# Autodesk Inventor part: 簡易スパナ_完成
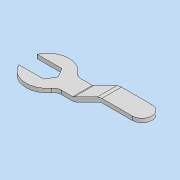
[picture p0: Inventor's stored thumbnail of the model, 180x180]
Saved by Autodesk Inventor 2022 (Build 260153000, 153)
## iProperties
Created: 2021-07
Part Number: 簡易スパナ_完成
Material: 一般
Document SubType Name: Modeling
Designer: DesignLab
Density: 1 g/cm^3
Appearance: 既定
Author: DesignLab
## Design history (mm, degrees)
sketch "スケッチ1"
  geometry: L1 (25, 0)-(-28, 0); L2 (-28, 0)-(-48, 10); L3 (-48, 10)-(-100, 10); 1 further point
  constraints: 6 end point, 1 horizontal, 1 parallel, 1 point on line
  dimensions: "d0" = 25 distance of point (0, 0) L1.start; "d1" = 100 horizontal distance of L3.end point (0, 0); "d2" = 10 distance between parallel lines of L1 L3; "d3" = 28 distance of L1.end point (0, 0); "d4" = 20 horizontal distance of L1.end L2.end
feature "押し出しサーフェス1" sketch "スケッチ1" dims "d5" = 40, "d6" = 0
fillet "フィレット1" dims "d7" = 5
feature "厚み1" dims "d8" = 3
sketch "スケッチ2"
  geometry: L1 (-49.18, 20)-(30.82, 20); L2 (-41.68, 12.5)-(23.32, 12.5); L3 (23.32, 27.5)-(-41.68, 27.5); C1 r 16.5 at (-49.18, 20); A1 r 7.5 centre (-41.68, 20) between (-41.68, 27.5) and (-41.68, 12.5); A2 r 7.5 centre (23.32, 20) between (23.32, 12.5) and (23.32, 27.5); 4 further points
  constraints: 8 end point, 6 point on circle, 4 tangent, 3 centre point, 2 point on line, 1 coincident, 1 horizontal, 1 midpoint, 1 parallel
  dimensions: "d9" = 33 diameter of C1; "d10" = 80 distance of L1.start L1.end; "d11" = 15 diameter of A2
extrude "押し出し1" sketch "スケッチ2" extent not by distance; stored distance "d12" = 0; taper "d13" = 0 deg
sketch "スケッチ3"
  geometry: L1 (-22.78, -7.5)-(-18.738, -0.5); L2 (-18.738, -0.5)-(-10.655, -0.5); L3 (-10.655, -0.5)-(-6.614, -7.5); L4 (-6.614, -7.5)-(-10.655, -14.5); L5 (-10.655, -14.5)-(-18.738, -14.5); L6 (-18.738, -14.5)-(-22.78, -7.5); L7 (-18.738, -0.5)-(-37.064, -0.5); L8 (-37.064, -0.5)-(-37.064, -14.5); L9 (-37.064, -14.5)-(-18.738, -14.5); L10 (-18.738, -14.5)-(-18.738, -0.5); 2 further points
  constraints: 20 end point, 2 parallel, 1 coincident, 1 horizontal, 1 perpendicular, 13 other
  dimensions: "d14" = 14 distance of L7.end L8.end
extrude "押し出し2" cut sketch "スケッチ3" extent not by distance; stored distance "d15" = 0; taper "d16" = 0 deg
fillet "フィレット2" dims "d17" = 6
node "ソリッド1"
body "Srf1"
